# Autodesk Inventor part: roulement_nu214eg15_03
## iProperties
Shininess: 64.0
Length Units: 11269
Angle Units: 11279
Time Units: 11290
Mass Units: 11283
Length Display Precision: 3
Angle Display Precision: 2
Compacted: True
Part Number: roulement_nu214eg15_03
Document SubType Name: Modeling
Created: 2005-02
Material: Par défaut
Designer: LEGERET Philippe
Density: 0.0
Volumn: 0.0
Area: 0.0
PropertySet Name: Model Information
Control State: 0
Master: False
Checked Out: False
Author: LEGERET Philippe
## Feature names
1. Base1
